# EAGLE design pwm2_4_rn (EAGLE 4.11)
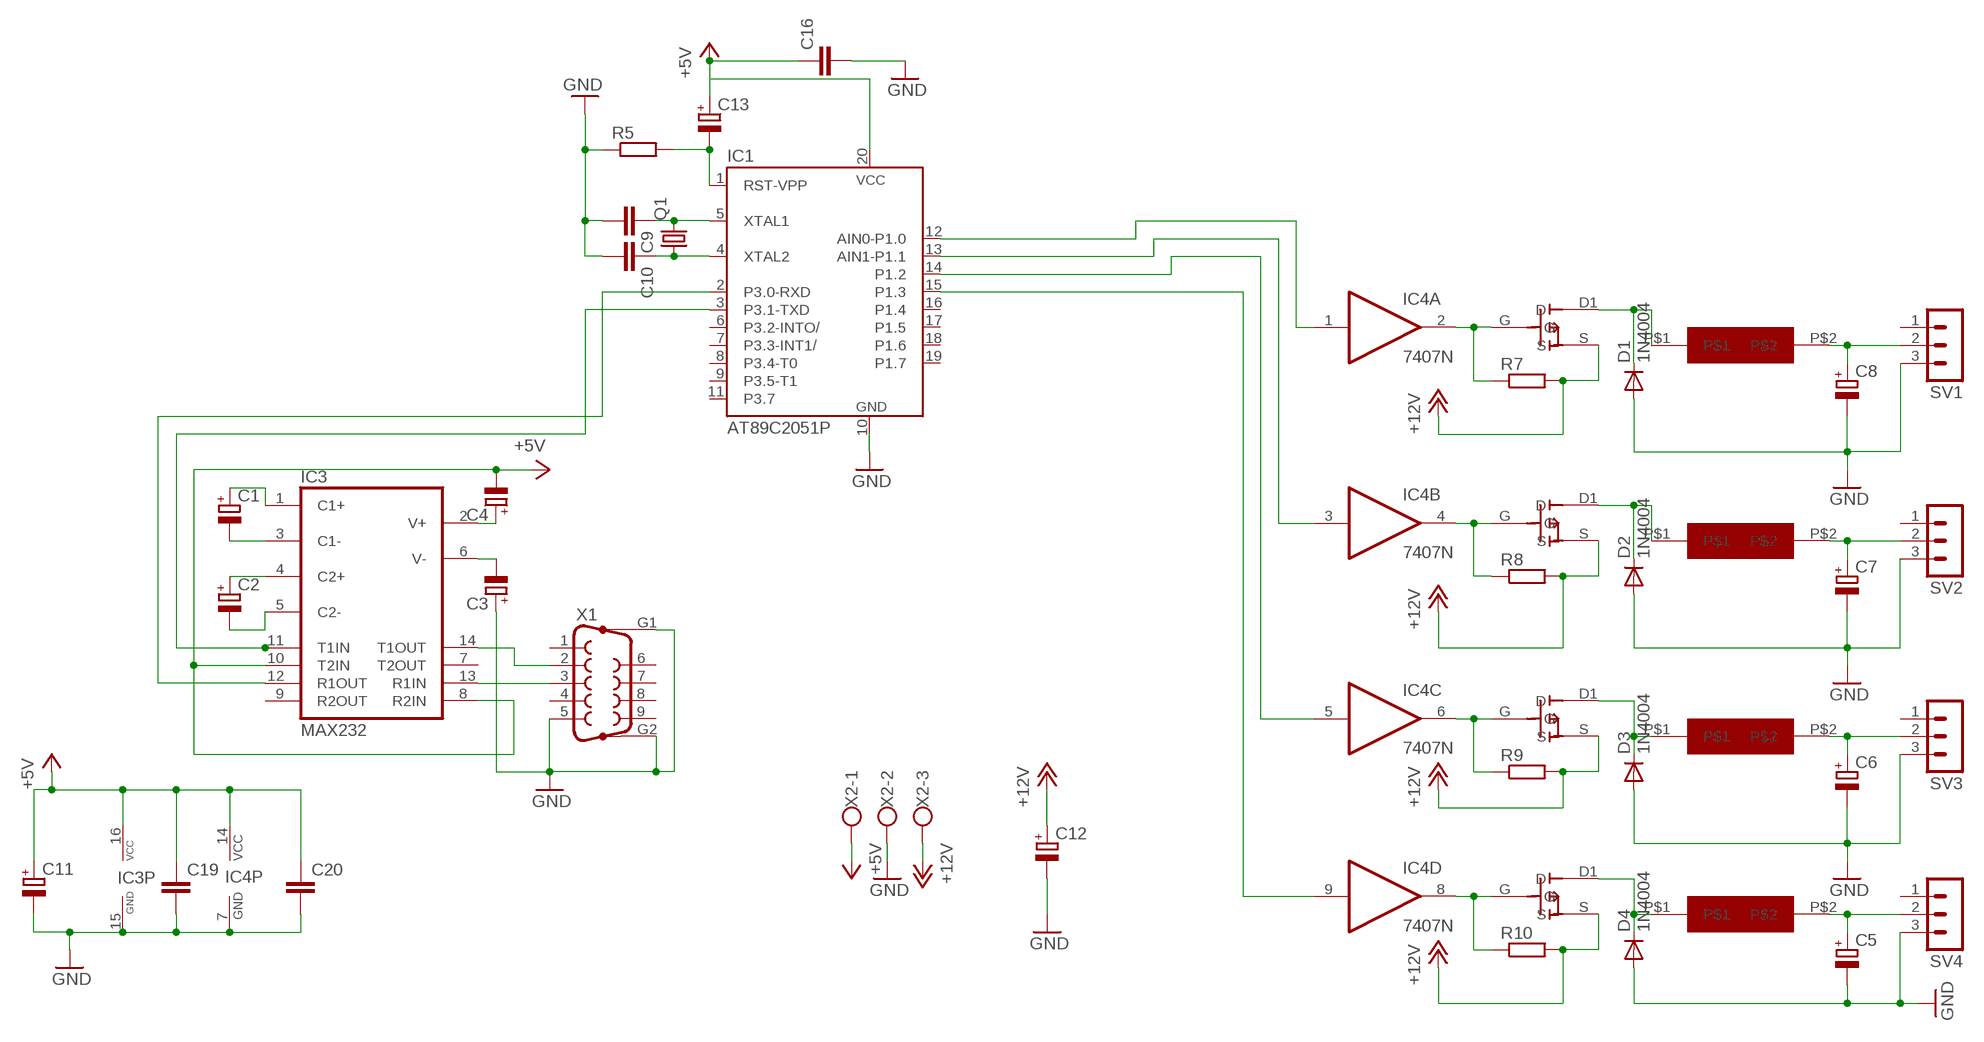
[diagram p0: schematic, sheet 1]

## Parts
C1  CPOL-EUE2.5-6  [E2,5-6]
C2  CPOL-EUE2.5-6  [E2,5-6]
C3  CPOL-EUE2.5-6  [E2,5-6]
C4  CPOL-EUE2.5-6  [E2,5-6]
C5  CPOL-EUE5-10.5  [E5-10,5]
C6  CPOL-EUE5-10.5  [E5-10,5]
C7  CPOL-EUE5-10.5  [E5-10,5]
C8  CPOL-EUE5-10.5  [E5-10,5]
C9  C-EU025-024X044  [C025-024X044]
C10  C-EU025-024X044  [C025-024X044]
C11  CPOL-EUE5-10.5  [E5-10,5]
C12  CPOL-EUE5-10.5  [E5-10,5]
C13  CPOL-EUE2.5-6  [E2,5-6]
C16  C-EU025-030X050  [C025-030X050]
C19  C-EU025-030X050  [C025-030X050]
C20  C-EU025-030X050  [C025-030X050]
D1  1N4004  [DO41-10]
D2  1N4004  [DO41-10]
D3  1N4004  [DO41-10]
D4  1N4004  [DO41-10]
IC1  AT89C2051P  [DIL20]
IC3  MAX232  [DIL16]
IC4  7407N  [DIL14]
Q1  CRYTALHC49S  [HC49/S]
R5  R-EU_0207/10  [0207/10]
R7  R-EU_0207/10  [0207/10]
R8  R-EU_0207/10  [0207/10]
R9  R-EU_0207/10  [0207/10]
R10  R-EU_0207/10  [0207/10]
SV1  MA03-1  [MA03-1]
SV2  MA03-1  [MA03-1]
SV3  MA03-1  [MA03-1]
SV4  MA03-1  [MA03-1]
U$2  IRF9024  [IRF9024]
U$3  IRF9024  [IRF9024]
U$4  IRF9024  [IRF9024]
U$5  IRF9024  [IRF9024]
U$6  REICHELTSPULE  [REICHELTSPULE]
U$7  REICHELTSPULE  [REICHELTSPULE]
U$8  REICHELTSPULE  [REICHELTSPULE]
U$9  REICHELTSPULE  [REICHELTSPULE]
X1  F09HP  [F09HP]
X2  AK300/3  [AK300/3]

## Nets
+5V: C4.- C11.+ C13.+ C16.1 C19.1 C20.1 IC1.20(VCC) IC3.8(R2IN) IC3.10(T2IN) IC3.16(VCC) IC4.14(P:VCC) X2.1
+12V: C12.+ R7.2 R8.2 R9.2 R10.2 U$2.S U$3.S U$4.S U$5.S X2.3
GND: C3.+ C5.- C6.- C7.- C8.- C9.2 C10.2 C11.- C12.- C16.2 C19.2 C20.2 D1.A D2.A D3.A D4.A IC1.10(GND) IC3.15(GND) IC4.7(P:GND) R5.1 SV1.3 SV2.3 SV3.3 SV4.3 X1.5 X1.G1 X1.G2 X2.2
N$2: IC1.2(P3.0-RXD) IC3.12(R1OUT)
N$6: IC1.3(P3.1-TXD) IC3.11(T1IN)
N$8: C1.+ IC3.1(C1+)
N$9: C1.- IC3.3(C1-)
N$10: C2.+ IC3.4(C2+)
N$11: C2.- IC3.5(C2-)
N$12: C3.- IC3.6(V-)
N$13: C4.+ IC3.2(V+)
N$18: D4.C U$5.D1(D) U$6.P$1
N$19: IC3.14(T1OUT) X1.2
N$21: C7.+ SV2.2 U$8.P$2
N$22: IC4.8(D:O) R10.1 U$5.G
N$23: D3.C U$4.D1(D) U$7.P$1
N$24: D2.C U$3.D1(D) U$8.P$1
N$25: D1.C U$2.D1(D) U$9.P$1
N$26: IC3.13(R1IN) X1.3
N$28: IC4.6(C:O) R9.1 U$4.G
N$29: IC1.14(P1.2) IC4.5(C:I)
N$36: IC4.2(A:O) R7.1 U$2.G
N$42: IC1.15(P1.3) IC4.9(D:I)
N$43: IC1.13(AIN1-P1.1) IC4.3(B:I)
N$44: IC1.12(AIN0-P1.0) IC4.1(A:I)
N$45: C9.1 IC1.5(XTAL1) Q1.2
N$46: C10.1 IC1.4(XTAL2) Q1.1
N$50: C13.- IC1.1(RST-VPP) R5.2
N$61: C8.+ SV1.2 U$9.P$2
N$62: C6.+ SV3.2 U$7.P$2
N$66: IC4.4(B:O) R8.1 U$3.G
N$68: C5.+ SV4.2 U$6.P$2
Unconnected: IC1.6(P3.2-INTO/) IC1.7(P3.3-INT1/) IC1.8(P3.4-T0) IC1.9(P3.5-T1) IC1.11(P3.7) IC1.16(P1.4) IC1.17(P1.5) IC1.18(P1.6) IC1.19(P1.7) IC3.7(T2OUT) IC3.9(R2OUT) IC4.10(E:O) IC4.11(E:I) IC4.12(F:O) IC4.13(F:I) SV1.1 SV2.1 SV3.1 SV4.1 X1.1 X1.4 X1.6 X1.7 X1.8 X1.9

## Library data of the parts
C1-C8 C11-C13 = rcl:CPOL-EU: POLARIZED CAPACITOR, European symbol
C9 C10 C16 C19 C20 = rcl:C-EU: CAPACITOR, European symbol
D1-D4 = diode:1N4004: DIODE
IC1 = atmel:AT89C2051: 80C31 MICROCONTROLLER 2 Kbytes FLASH 2.7 V
IC3 = maxim:MAX232: RS232 TRANSEIVER
IC4 = 74xx-eu:74*07: Hex BUFFER, open collector high-voltage output
Q1 = crystal:CRYTAL: CRYSTAL
R5 R7-R10 = rcl:R-EU_: RESISTOR, European symbol
SV1-SV4 = con-lstb:MA03-1: PIN HEADER
U$2-U$5 = Fets:IRF9024
U$6-U$9 = spule:REICHELTSPULE
X1 = con-subd:F09HP: SUB-D
X2 = con-ptr500:AK300/3: CONNECTOR

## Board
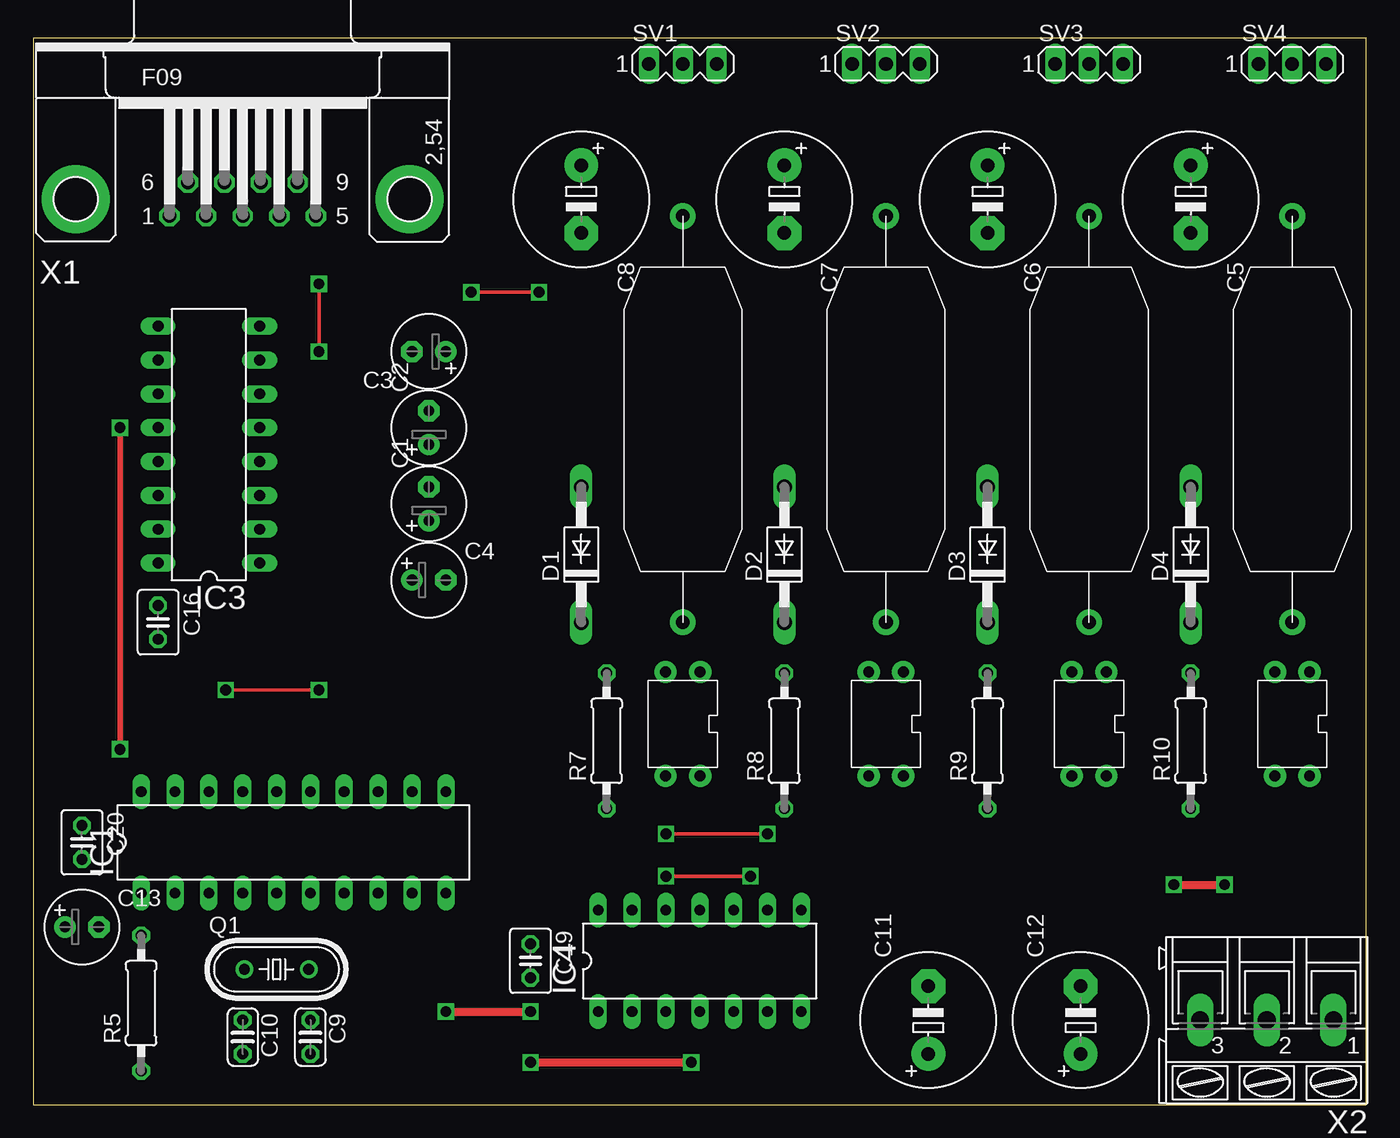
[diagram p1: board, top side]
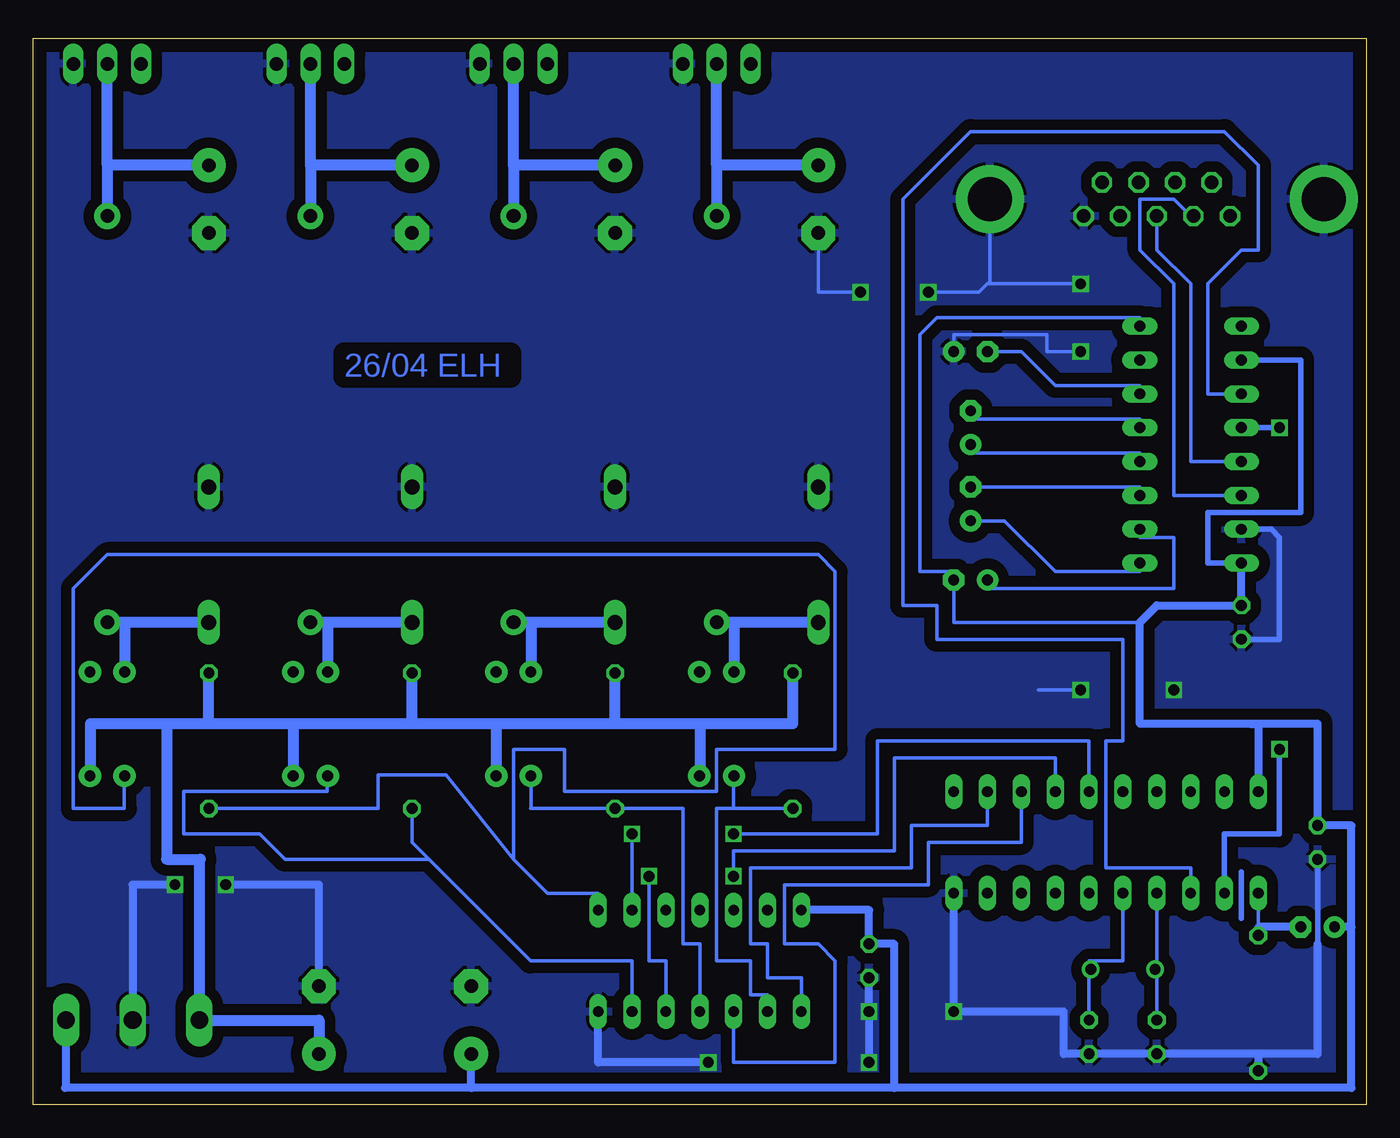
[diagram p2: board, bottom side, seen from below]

Size 100 x 80 mm. Coordinates in mm from the lower left corner, seen from the top.
Outline: 0,0 100,0 100,80 0,80 0,0
Copper layers (1*16): Top 0.035mm / dielectric 1.5mm / Bottom 0.035mm
Design rules "default": minimum track width 10mil, minimum drill 24mil, track to track 8mil, track to pad 8mil, pad to pad 8mil, via to via 8mil, smd to smd 8mil, copper to edge 40mil, drill to drill 8mil, minimum pad ring 10mil, minimum via ring 8mil, stop-mask expansion 4mil, vias tented up to drill 0mil, thermal gap 10mil

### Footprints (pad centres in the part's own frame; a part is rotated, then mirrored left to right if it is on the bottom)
E2,5-6 = drill 0.813 pad 1.6 round: + -1.27,0 | drill 0.813 pad 1.6 octagon: - 1.27,0
E5-10,5 = drill 1.016 pad 2.54 round: + -2.54,0 | drill 1.016 pad 2.54 octagon: - 2.54,0
C025-024X044 = drill 0.813 octagon: 1 -1.27,0; 2 1.27,0
C025-030X050 = drill 0.813 octagon: 1 -1.27,0; 2 1.27,0
DO41-10 = drill 1.118 long: A 5.08,0; C -5.08,0
DIL20 = drill 0.813 long: 1 -11.43,-3.81; 2 -8.89,-3.81; 3 -6.35,-3.81; 4 -3.81,-3.81; 5 -1.27,-3.81; 6 1.27,-3.81; 7 3.81,-3.81; 8 6.35,-3.81; 9 8.89,-3.81; 10 11.43,-3.81; 11 11.43,3.81; 12 8.89,3.81; 13 6.35,3.81; 14 3.81,3.81; 15 1.27,3.81; 16 -1.27,3.81; 17 -3.81,3.81; 18 -6.35,3.81; 19 -8.89,3.81; 20 -11.43,3.81
DIL16 = drill 0.813 long: 1 -8.89,-3.81; 2 -6.35,-3.81; 3 -3.81,-3.81; 4 -1.27,-3.81; 5 1.27,-3.81; 6 3.81,-3.81; 7 6.35,-3.81; 8 8.89,-3.81; 9 8.89,3.81; 10 6.35,3.81; 11 3.81,3.81; 12 1.27,3.81; 13 -1.27,3.81; 14 -3.81,3.81; 15 -6.35,3.81; 16 -8.89,3.81
DIL14 = drill 0.8 long: 1 -7.62,-3.81; 2 -5.08,-3.81; 3 -2.54,-3.81; 4 0,-3.81; 5 2.54,-3.81; 6 5.08,-3.81; 7 7.62,-3.81; 8 7.62,3.81; 9 5.08,3.81; 10 2.54,3.81; 11 0,3.81; 12 -2.54,3.81; 13 -5.08,3.81; 14 -7.62,3.81
HC49/S = drill 0.813 round: 1 -2.413,0; 2 2.413,0
0207/10 = drill 0.813 octagon: 1 -5.08,0; 2 5.08,0
MA03-1 = drill 1.016 long: 1 -2.54,0; 2 0,0; 3 2.54,0
IRF9024 = drill 0.813 pad 1.676 round: D1 -3.9,-1.3; D2 -3.9,1.3; G 3.9,-1.3; S 3.9,1.3
REICHELTSPULE = drill 1.016 pad 1.93 round: P$1 -15.24,0; P$2 15.24,0
F09HP = drill 1.016 octagon: 1 -5.486,-1.27; 2 -2.743,-1.27; 3 0,-1.27; 4 2.743,-1.27; 5 5.486,-1.27; 6 -4.115,1.27; 7 -1.372,1.27; 8 1.372,1.27; 9 4.115,1.27 | drill 3.302 pad 5.08 round: G1 -12.522,0; G2 12.522,0
AK300/3 = drill 1.321 long: 1 -5.004,0; 2 0,0; 3 5.004,0

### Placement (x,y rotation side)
C1  29.68,45.08 90 top
C2  29.68,50.8 90 top
C3  29.68,56.51 180 top
C4  29.68,39.37 0 top
C5  86.83,67.94 270 top
C6  71.59,67.94 270 top
C7  56.35,67.94 270 top
C8  41.11,67.94 270 top
C9  20.79,5.08 270 top
C10  15.71,5.08 270 top
C11  67.14,6.34 90 top
C12  78.58,6.34 90 top
C13  3.64,13.33 0 top
C16  9.36,36.19 270 top
C19  37.3,10.79 270 top
C20  3.64,19.68 270 top
D1  41.11,41.27 90 top
D2  56.35,41.27 90 top
D3  71.59,41.27 90 top
D4  86.83,41.27 90 top
IC1  19.52,19.68 0 top
IC3  13.17,49.53 90 top
IC4  50,10.79 0 top
Q1  18.25,10.16 0 top
R5  8.09,7.62 90 top
R7  43.02,27.3 90 top
R8  56.35,27.3 90 top
R9  71.59,27.3 90 top
R10  86.83,27.3 90 top
SV1  48.73,78.1 0 top
SV2  63.97,78.1 0 top
SV3  79.21,78.1 0 top
SV4  94.45,78.1 0 top
U$2  48.73,28.57 270 top
U$3  63.97,28.57 270 top
U$4  79.21,28.57 270 top
U$5  94.45,28.57 270 top
U$6  94.45,51.43 90 top
U$7  79.21,51.43 90 top
U$8  63.97,51.43 90 top
U$9  48.73,51.43 90 top
X1  15.71,67.94 0 top
X2  92.55,6.34 180 top

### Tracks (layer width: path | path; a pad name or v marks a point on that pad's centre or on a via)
+5V
  Bottom 0.254: IC3.8 16.98,59.05 32.22,59.05 33.49,57.78 33.49,40 30.95,40 C4.- 30.95,36.19 16.98,36.19
  Bottom 0.406: IC3.16 11.9,40.64 11.9,44.45 4.92,44.45 4.92,55.88 IC3.10
  Bottom 0.61: X2.1 97.55,1.34 97.62,1.27 67.14,1.27 | 67.14,1.27 C11.+ | 35.39,1.27 67.14,1.27 | 35.39,1.27 35.39,12.06 C19.1 37.3,14.6 IC4.14 | 1.1,13.33 1.1,1.27 35.39,1.27 | 1.1,13.33 1.1,20.95 C20.1 3.64,28.57 8.73,28.57 | IC1.20 8.09,28.57 8.73,28.57 | 1.1,13.33 C13.+ | 8.73,28.57 16.98,28.57 16.98,36.19 15.71,37.46 C16.1 IC3.16
+12V
  Bottom 0.813: 90,28.57 90,18.41 87.47,18.41 87.54,18.33 X2.3 78.58,6.34 C12.+ 78.58,3.17 | 90,28.57 95.72,28.57 95.72,24.76 95.75,24.73 U$5.S | 50,28.57 43.02,28.57 R7.2 | 50,28.57 56.35,28.57 | 56.35,28.57 65.24,28.57 | 65.24,28.57 71.59,28.57 | 71.59,28.57 80.48,28.57 | 80.48,28.57 86.83,28.57 | 86.83,28.57 90,28.57 | U$2.S 50.03,24.73 50,24.76 50,28.57 | U$4.S 80.51,28.54 80.48,28.57 | U$3.S 65.27,28.54 65.24,28.57 | 56.35,28.57 R8.2 | 71.59,28.57 R9.2 | 86.83,28.57 R10.2
GND  (via drill 0.81)
  Top 0.254: v21.42,56.51 v21.42,61.59 | v32.85,60.96 v37.94,60.96 | v14.44,31.11 v21.42,31.11
  Top 0.61: v85.56,16.5 v89.37,16.5 | v30.95,6.98 v37.3,6.98 | v37.3,3.17 v49.37,3.17
  Bottom 0.254: X1.G2 28.23,61.77 28.41,61.59 | v21.42,61.59 28.41,61.59 | v21.42,56.51 23.96,56.51 23.96,57.78 30.95,57.78 C3.+ | v37.94,60.96 41.11,60.96 C8.- | v32.85,60.96 29.04,60.96 28.41,61.59 | v21.42,31.11 24.6,31.11
  Bottom 0.406: 3.64,12.06 C20.2 | 7.46,43.18 IC3.15 7.14,43.18 6.5,42.54 6.5,34.92 C16.2
  Bottom 0.61: C12.- 78.58,16.5 v85.56,16.5 | v89.37,16.5 92.55,16.5 X2.2 | C19.2 v37.3,6.98 v37.3,3.17 | IC1.10 v30.95,6.98 22.7,6.98 22.7,3.8 C9.2 C10.2 8.09,3.8 | v49.37,3.17 57.62,3.17 IC4.7 | 8.09,3.8 R5.1 | 8.09,3.8 3.64,3.8 3.64,12.06
  pour Bottom (isolate 0.813): 0.47,79.37 99.53,79.37 100.16,0.63 0.47,0.63
N$1
  Bottom 0.406: 9.36,13.97 9.36,17.46
N$2  (via drill 0.81)
  Top 0.406: v6.5,26.66 v6.5,50.8
  Bottom 0.406: IC1.2 10.63,20.31 6.5,20.31 v6.5,26.66 | v6.5,50.8 IC3.12
N$6
  Bottom 0.254: IC3.11 11.9,53.34 11.9,61.59 9.36,64.13 8.09,64.13 8.09,70.48 10.63,73.02 29.68,73.02 34.76,67.94 34.76,37.46 32.22,37.46 32.22,34.92 18.25,34.92 18.25,27.3 19.52,27.3 19.52,17.77 13.17,17.77 IC1.3
N$8
  Bottom 0.254: C1.+ 27.14,43.81 23.33,40 16.98,40 IC3.1
N$9
  Bottom 0.254: C1.- 16.98,46.35 IC3.3
N$10
  Bottom 0.254: IC3.4 16.98,48.89 29.68,48.89 C2.+
N$11
  Bottom 0.254: IC3.5 16.98,51.43 29.68,51.43 C2.-
N$12
  Bottom 0.254: C3.- 25.87,56.51 23.33,53.97 16.98,53.97 IC3.6
N$13
  Bottom 0.254: IC3.2 16.98,42.54 14.44,42.54 14.44,38.73 28.41,38.73 C4.+
N$18
  Bottom 0.813: D4.C 93.18,36.19 | 93.18,36.19 U$6.P$1 | U$5.D1 93.15,36.16 93.18,36.19
N$19
  Bottom 0.254: IC3.14 14.44,45.72 14.44,61.59 16.98,64.13 16.98,67.94 14.44,67.94 13.17,66.67 X1.2
N$21
  Bottom 0.813: 63.97,70.48 U$8.P$2 | 63.97,70.48 SV2.2 | C7.+ 63.97,70.48
N$22
  Bottom 0.254: 63.97,18.41 69.05,24.76 74.13,24.76 74.13,22.22 R10.1 | 63.97,18.41 61.43,15.87 57.62,15.87 IC4.8 | 63.97,18.41 63.97,26.66 60.16,26.66 60.16,23.49 48.73,23.49 48.73,26.66 39.84,26.66 39.84,40 41.11,41.27 94.45,41.27 96.99,38.73 96.99,22.22 93.18,22.22 93.18,24.76 U$5.G
N$23
  Bottom 0.813: D3.C 77.94,36.19 | 77.94,36.19 U$7.P$1 | U$4.D1 77.91,36.16 77.94,36.19
N$24
  Bottom 0.813: D2.C 62.7,36.19 | 62.7,36.19 U$8.P$1 | U$3.D1 62.67,36.16 62.7,36.19
N$25
  Bottom 0.813: D1.C 47.46,36.19 | 47.46,36.19 U$9.P$1 | U$2.D1 47.43,36.16 47.46,36.19
N$26
  Bottom 0.254: IC3.13 13.17,48.26 13.17,61.59 15.71,64.13 X1.3
N$28
  Bottom 0.254: 70.32,18.41 71.59,19.68 R9.1 | 70.32,18.41 62.7,10.79 55.08,10.79 IC4.6 | 70.32,18.41 81.11,18.41 83.02,20.31 88.73,20.31 88.73,23.49 77.94,23.49 77.94,24.76 U$4.G
N$29  (via drill 0.81)
  Top 0.254: v47.46,17.14 v53.81,17.14
  Bottom 0.254: IC1.14 23.33,26.03 35.39,26.03 35.39,19.04 47.46,19.04 v47.46,17.14 | v53.81,17.14 53.81,10.79 52.54,10.79 IC4.5
N$36
  Bottom 0.254: 47.46,22.22 47.46,24.76 U$2.G | 47.46,22.22 48.73,22.22 48.73,10.79 46.19,10.79 46.19,8.25 44.92,8.25 IC4.2 | 47.46,22.22 R7.1
N$42  (via drill 0.81)
  Top 0.254: v47.46,20.31 v55.08,20.31
  Bottom 0.254: IC1.15 20.79,27.3 36.66,27.3 36.66,20.31 v47.46,20.31 | v55.08,20.31 IC4.9
N$43
  Bottom 0.254: IC4.3 47.46,3.17 39.84,3.17 39.84,10.79 41.11,12.06 43.65,12.06 43.65,16.5 32.85,16.5 32.85,19.68 25.87,19.68 IC1.13
N$44
  Bottom 0.254: IC4.1 42.38,9.52 44.92,9.52 44.92,12.06 46.19,12.06 46.19,17.77 34.12,17.77 34.12,20.95 28.41,20.95 IC1.12
N$45
  Bottom 0.254: IC1.5 18.25,10.79 20.79,10.79 Q1.2 20.79,9.52 C9.1
N$46
  Bottom 0.254: C10.1 15.71,9.52 Q1.1 15.71,10.79 IC1.4
N$50
  Bottom 0.254: R5.2 IC1.1
  Bottom 0.61: C13.- 8.09,13.33 R5.2
N$61
  Bottom 0.813: 48.73,70.48 U$9.P$2 | 48.73,70.48 SV1.2 | C8.+ 48.73,70.48
N$62
  Bottom 0.254: 79.21,67.3 U$7.P$2
  Bottom 0.813: 79.21,70.48 79.21,67.3 | 79.21,70.48 SV3.2 | C6.+ 79.21,70.48
N$66
  Bottom 0.254: IC4.4 50,12.06 51.27,12.06 51.27,22.22 R8.1 62.7,22.22 62.67,22.25 U$3.G 62.7,24.76
N$68
  Bottom 0.813: 94.45,70.48 U$6.P$2 | 94.45,70.48 SV4.2 | C5.+ 94.45,70.48

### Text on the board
Bottom: 26/04 ELH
